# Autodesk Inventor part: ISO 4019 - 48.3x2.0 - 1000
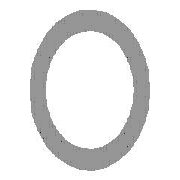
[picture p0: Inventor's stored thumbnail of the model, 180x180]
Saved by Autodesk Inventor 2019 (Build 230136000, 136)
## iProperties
IsCustomPart: 1
Created: 2018-01
Part Number: ISO 4019 - 48.3x2.0 - 1000
Material: Acier, doux
Description: Aciers de construction - Coupes creuses profilées formées à froid, soudées
Document SubType Name: Modeling
Standard: ISO
Designer: Fabian Perrée
Standard Revision: Second edition 2001-09-01
Standards Organization: ISO
Language: fr-FR
Size Designation: 48.3x2.0
Categories: <MemberInstance><Categories><Category DisplayName="Profilés" InternalName="089c4875-fa83-4c05-b084-43b9cc11f5ed" Mnemonic="GRDR"><CategoryParameter DisplayName=
Stock Number: 48.3x2.0
Density: 7.85 g/cm^3
Appearance: Semi-poli
Mass: 2169.32 g
Surface Area: 2784.02 cm^2
Volume: 276.347 cm^3
G_L: 1000,000 mm
G_W: 48,300 mm
G_H: 48,300 mm
+F65DF18C-8240-4B37-BE7E-B19A84124B65+DETAILDECOUPE1: Grugeage
+777B3F36-A96D-4E13-B6C7-D3E31DCB894B+DETAILDECOUPE2: Grugeage
_CCFamilyMember: 14
_CCFamilyDisplayName: ISO 4019 (Profils creux circulaires - Formés à froid) - Aciers de construction - Coupes creuses profilées formées à froid, soudées — ISO 4019 (Profils creux cir
_FrameMemberDoc: Frame Member File
_Version: 15.0.0
_GetPNFromCC: 1
Author: Fabian Perrée
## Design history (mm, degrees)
node "Plan de départ"
node "Plan de fin"
sketch "Esquisse"
  geometry: C1 r 22.15 at (0, 0); C2 r 24.15 at (0, 0); 2 further points
  constraints: 3 coincident, 2 centre point
  dimensions: "d0" = 48.3 diameter of C2 (= G_H); "d1" = 2 radial gap between concentric circles of C2 C1 (= G_T)
extrude "Corps" new body sketch "Esquisse" stored distance "d2" = 1000 (= G_L); taper "d3" = 0 deg
node "Driven Length"
  sketch "Sketch3"
    geometry: L1 (0, 0)-(10, 0) reference
    constraints: 2 end point, 1 horizontal
  workplane "Work Plane3"
  sketch "Sketch4"
    geometry: L1 (-2, 0)-(12, 0) reference; L2 (-2, 1000)-(12, 1000) reference
    dimensions: "d7" = 1000 distance between parallel lines of L1 L2 (derived)
body "Solid1"
feature "Sculpter1"
feature "Combiner1"
feature "Sculpter3"
feature "Combiner3"
body "Srf17"
body "Srf18"
node "Solide7"
body "Srf20"
body "Srf21"
node "Solide8"
feature "Surface1"
body "Srf16"
feature "Carreau délimité11" dims "d28" = 5, "d29" = 0
feature "Carreau délimité12" dims "d30" = 5, "d31" = 0
feature "Surface3"
body "Srf19"
feature "Carreau délimité13" dims "d32" = 5, "d33" = 0
feature "Carreau délimité14" dims "d34" = 5, "d35" = 0
other parameters: "G_H" = 48.3 [user parameter; used in 1 equation term], "G_T" = 2 [user parameter; used in 1 equation term], "G_L" = 1000 (= d7) [user parameter; used in 1 equation term], "G_OFFSET_START" = 0 [user parameter; used in 1 equation term], "G_OFFSET_END" = 0 [user parameter; used in 1 equation term], "d4" = 0 (computed from G_OFFSET_START), "d5" = 1000 (= G_OFFSET_END + B_L), "B_L" = 1000 [user parameter; used in 1 equation term], "d6" = 90 deg, "MAS" = 0.228 [user parameter]
